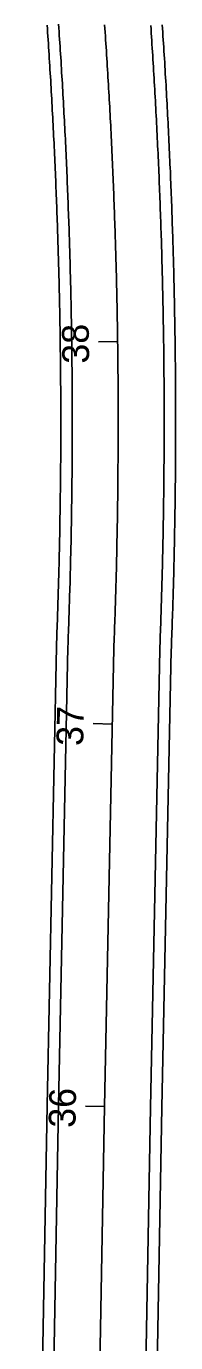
# Model space of a CAD drawing. Extents: x 2318076 to 2324211, y 613525 to 629939.
# Drawn here: x 2318913.8 to 2318952.8, y 618473.3 to 618817.4 of the extents above; entities that cross this region are included whole.
import ezdxf

# ---------------------------------------------------------------- set-up
doc = ezdxf.new("R2010")
doc.units = 0
for name, color, linetype in [('GE_P_CL_50', 7, 'Continuous'), ('PV_P_EOP', 7, 'Continuous'), ('PV_P_Shoulder', 7, 'Continuous')]:
    doc.layers.add(name, color=color, linetype=linetype)

msp = doc.modelspace()

# ---------------------------------------------------------------- linework, layer by layer
at = {"layer": 'GE_P_CL_50'}
for p, q in [((2318937.67, 618735), (2318932.67, 618734.93)), ((2318936.28, 618635.02), (2318931.28, 618635.12)), ((2318934.25, 618535.04), (2318929.25, 618535.14))]:
    msp.add_line(p, q, dxfattribs=at)
msp.add_lwpolyline([(2318928.83, 618235.09), (2318934.25, 618535.04), (2318936.67, 618654.75), (2318936.71, 618655.73), (2318936.74, 618656.7), (2318936.78, 618657.68), (2318936.82, 618658.66), (2318936.85, 618659.63), (2318936.89, 618660.61), (2318936.92, 618661.58), (2318936.95, 618662.56), (2318936.99, 618663.54), (2318937.02, 618664.51), (2318937.05, 618665.49), (2318937.08, 618666.47), (2318937.11, 618667.44), (2318937.14, 618668.42), (2318937.17, 618669.4), (2318937.2, 618670.37), (2318937.22, 618671.35), (2318937.25, 618672.33), (2318937.28, 618673.3), (2318937.3, 618674.28), (2318937.33, 618675.26), (2318937.35, 618676.23), (2318937.38, 618677.21), (2318937.4, 618678.18), (2318937.42, 618679.16), (2318937.44, 618680.14), (2318937.46, 618681.12), (2318937.48, 618682.09), (2318937.5, 618683.07), (2318937.52, 618684.05), (2318937.54, 618685.02), (2318937.56, 618686), (2318937.58, 618686.98), (2318937.6, 618687.95), (2318937.61, 618688.93), (2318937.63, 618689.91), (2318937.64, 618690.88), (2318937.66, 618691.86), (2318937.67, 618692.84), (2318937.68, 618693.81), (2318937.7, 618694.79), (2318937.71, 618695.77), (2318937.72, 618696.74), (2318937.73, 618697.72), (2318937.74, 618698.7), (2318937.75, 618699.67), (2318937.76, 618700.65), (2318937.79, 618705.54), (2318937.8, 618706.51), (2318937.8, 618707.49), (2318937.81, 618708.47), (2318937.81, 618709.44), (2318937.81, 618710.42), (2318937.81, 618711.4), (2318937.82, 618712.37), (2318937.82, 618713.35), (2318937.82, 618714.33), (2318937.82, 618715.31), (2318937.81, 618716.28), (2318937.81, 618717.26), (2318937.81, 618718.24), (2318937.81, 618719.21), (2318937.8, 618720.19), (2318937.8, 618721.17), (2318937.79, 618722.14), (2318937.79, 618723.12), (2318937.78, 618724.1), (2318937.78, 618725.07), (2318937.77, 618726.05), (2318937.76, 618727.03), (2318937.75, 618728.01), (2318937.74, 618728.98), (2318937.73, 618729.96), (2318937.72, 618730.94), (2318937.71, 618731.91), (2318937.7, 618732.89), (2318937.69, 618733.87), (2318937.67, 618734.84), (2318937.66, 618735.82), (2318937.65, 618736.8), (2318937.63, 618737.77), (2318937.61, 618738.75), (2318937.6, 618739.73), (2318937.58, 618740.7), (2318937.56, 618741.68), (2318937.55, 618742.66), (2318937.53, 618743.63), (2318937.51, 618744.61), (2318937.49, 618745.59), (2318937.47, 618746.56), (2318937.45, 618747.54), (2318937.42, 618748.52), (2318937.4, 618749.49), (2318937.38, 618750.47), (2318937.36, 618751.45), (2318937.33, 618752.42), (2318937.31, 618753.4), (2318937.28, 618754.38), (2318937.25, 618755.35), (2318937.23, 618756.33), (2318937.2, 618757.31), (2318937.17, 618758.28), (2318937.14, 618759.26), (2318937.11, 618760.24), (2318937.08, 618761.21), (2318937.05, 618762.19), (2318937.02, 618763.17), (2318936.99, 618764.14), (2318936.96, 618765.12), (2318936.93, 618766.1), (2318936.89, 618767.07), (2318936.86, 618768.05), (2318936.82, 618769.02), (2318936.79, 618770), (2318936.75, 618770.98), (2318936.71, 618771.95), (2318936.68, 618772.93), (2318936.64, 618773.91), (2318936.6, 618774.88), (2318936.56, 618775.86), (2318936.52, 618776.83), (2318936.48, 618777.81), (2318936.44, 618778.79), (2318936.4, 618779.76), (2318936.35, 618780.74), (2318936.31, 618781.71), (2318936.27, 618782.69), (2318936.22, 618783.67), (2318936.18, 618784.64), (2318936.13, 618785.62), (2318936.09, 618786.59), (2318936.04, 618787.57), (2318935.99, 618788.54), (2318935.94, 618789.52), (2318935.9, 618790.5), (2318935.85, 618791.47), (2318935.8, 618792.45), (2318935.75, 618793.42), (2318935.7, 618794.4), (2318935.64, 618795.37), (2318935.59, 618796.35), (2318935.54, 618797.33), (2318935.48, 618798.3), (2318935.43, 618799.28), (2318935.38, 618800.25), (2318935.32, 618801.23), (2318935.26, 618802.2), (2318935.21, 618803.18), (2318935.15, 618804.15), (2318935.09, 618805.13), (2318935.03, 618806.1), (2318934.97, 618807.08), (2318934.91, 618808.05), (2318934.85, 618809.03), (2318934.79, 618810), (2318934.73, 618810.98), (2318934.67, 618811.95), (2318934.61, 618812.93), (2318934.54, 618813.9), (2318934.48, 618814.88), (2318934.41, 618815.85), (2318934.35, 618816.83), (2318934.28, 618817.8)], dxfattribs=at)
at = {"layer": 'PV_P_EOP'}
for points in [[(2318916.83, 618235.27), (2318922.25, 618535.27), (2318924.67, 618655.1), (2318924.72, 618656.18), (2318924.75, 618657.15), (2318924.79, 618658.12), (2318924.82, 618659.09), (2318924.86, 618660.06), (2318924.89, 618661.03), (2318924.93, 618662), (2318924.96, 618662.96), (2318924.99, 618663.93), (2318925.02, 618664.9), (2318925.05, 618665.87), (2318925.08, 618666.84), (2318925.11, 618667.81), (2318925.14, 618668.78), (2318925.17, 618669.75), (2318925.2, 618670.71), (2318925.23, 618671.68), (2318925.25, 618672.65), (2318925.28, 618673.62), (2318925.31, 618674.59), (2318925.33, 618675.56), (2318925.36, 618676.53), (2318925.38, 618677.5), (2318925.4, 618678.47), (2318925.42, 618679.43), (2318925.45, 618680.4), (2318925.47, 618681.37), (2318925.49, 618682.34), (2318925.51, 618683.31), (2318925.53, 618684.28), (2318925.55, 618685.25), (2318925.56, 618686.22), (2318925.58, 618687.19), (2318925.6, 618688.16), (2318925.61, 618689.13), (2318925.63, 618690.09), (2318925.64, 618691.06), (2318925.66, 618692.03), (2318925.67, 618693), (2318925.69, 618693.97), (2318925.7, 618694.94), (2318925.71, 618695.91), (2318925.72, 618696.88), (2318925.73, 618697.85), (2318925.74, 618698.82), (2318925.75, 618699.79), (2318925.76, 618700.75), (2318925.79, 618705.61), (2318925.8, 618706.57), (2318925.8, 618707.54), (2318925.81, 618708.51), (2318925.81, 618709.48), (2318925.81, 618710.45), (2318925.81, 618711.42), (2318925.82, 618712.39), (2318925.82, 618713.36), (2318925.82, 618714.33), (2318925.82, 618715.29), (2318925.81, 618716.26), (2318925.81, 618717.23), (2318925.81, 618718.2), (2318925.81, 618719.17), (2318925.8, 618720.14), (2318925.8, 618721.11), (2318925.79, 618722.08), (2318925.79, 618723.05), (2318925.78, 618724.02), (2318925.78, 618724.99), (2318925.77, 618725.96), (2318925.76, 618726.93), (2318925.75, 618727.89), (2318925.74, 618728.86), (2318925.73, 618729.83), (2318925.72, 618730.8), (2318925.71, 618731.77), (2318925.7, 618732.74), (2318925.69, 618733.71), (2318925.67, 618734.68), (2318925.66, 618735.65), (2318925.65, 618736.62), (2318925.63, 618737.59), (2318925.62, 618738.56), (2318925.6, 618739.52), (2318925.58, 618740.49), (2318925.57, 618741.46), (2318925.55, 618742.43), (2318925.53, 618743.4), (2318925.51, 618744.37), (2318925.49, 618745.34), (2318925.47, 618746.31), (2318925.45, 618747.28), (2318925.43, 618748.25), (2318925.41, 618749.22), (2318925.38, 618750.18), (2318925.36, 618751.15), (2318925.33, 618752.12), (2318925.31, 618753.09), (2318925.28, 618754.06), (2318925.26, 618755.03), (2318925.23, 618756), (2318925.21, 618756.97), (2318925.18, 618757.94), (2318925.15, 618758.9), (2318925.12, 618759.87), (2318925.09, 618760.84), (2318925.06, 618761.81), (2318925.03, 618762.78), (2318925, 618763.75), (2318924.97, 618764.72), (2318924.93, 618765.69), (2318924.9, 618766.65), (2318924.86, 618767.62), (2318924.83, 618768.59), (2318924.79, 618769.56), (2318924.76, 618770.53), (2318924.72, 618771.5), (2318924.69, 618772.47), (2318924.65, 618773.43), (2318924.61, 618774.4), (2318924.57, 618775.37), (2318924.53, 618776.34), (2318924.49, 618777.31), (2318924.45, 618778.28), (2318924.41, 618779.24), (2318924.37, 618780.21), (2318924.32, 618781.18), (2318924.28, 618782.15), (2318924.24, 618783.12), (2318924.19, 618784.09), (2318924.15, 618785.05), (2318924.1, 618786.02), (2318924.05, 618786.99), (2318924.01, 618787.96), (2318923.96, 618788.93), (2318923.91, 618789.89), (2318923.86, 618790.86), (2318923.81, 618791.83), (2318923.76, 618792.8), (2318923.71, 618793.77), (2318923.66, 618794.73), (2318923.61, 618795.7), (2318923.56, 618796.67), (2318923.5, 618797.64), (2318923.45, 618798.61), (2318923.39, 618799.57), (2318923.34, 618800.54), (2318923.28, 618801.51), (2318923.23, 618802.48), (2318923.17, 618803.44), (2318923.11, 618804.41), (2318923.05, 618805.38), (2318923, 618806.35), (2318922.94, 618807.31), (2318922.88, 618808.28), (2318922.82, 618809.25), (2318922.75, 618810.22), (2318922.69, 618811.18), (2318922.63, 618812.15), (2318922.57, 618813.12), (2318922.5, 618814.08), (2318922.44, 618815.05), (2318922.37, 618816.02), (2318922.31, 618816.99), (2318922.24, 618817.95)], [(2318940.83, 618234.92), (2318946.25, 618534.81), (2318948.67, 618654.4), (2318948.7, 618655.27), (2318948.74, 618656.25), (2318948.77, 618657.24), (2318948.81, 618658.22), (2318948.84, 618659.2), (2318948.88, 618660.19), (2318948.91, 618661.17), (2318948.95, 618662.16), (2318948.98, 618663.14), (2318949.01, 618664.13), (2318949.04, 618665.11), (2318949.07, 618666.09), (2318949.1, 618667.08), (2318949.13, 618668.06), (2318949.16, 618669.05), (2318949.19, 618670.03), (2318949.22, 618671.01), (2318949.25, 618672), (2318949.27, 618672.98), (2318949.3, 618673.97), (2318949.32, 618674.95), (2318949.35, 618675.94), (2318949.37, 618676.92), (2318949.4, 618677.9), (2318949.42, 618678.89), (2318949.44, 618679.87), (2318949.46, 618680.86), (2318949.48, 618681.84), (2318949.5, 618682.83), (2318949.52, 618683.81), (2318949.54, 618684.79), (2318949.56, 618685.78), (2318949.58, 618686.76), (2318949.59, 618687.75), (2318949.61, 618688.73), (2318949.63, 618689.72), (2318949.64, 618690.7), (2318949.66, 618691.69), (2318949.67, 618692.67), (2318949.68, 618693.66), (2318949.7, 618694.64), (2318949.71, 618695.62), (2318949.72, 618696.61), (2318949.73, 618697.59), (2318949.74, 618698.58), (2318949.75, 618699.56), (2318949.76, 618700.55), (2318949.79, 618705.46), (2318949.8, 618706.45), (2318949.8, 618707.44), (2318949.81, 618708.42), (2318949.81, 618709.41), (2318949.81, 618710.39), (2318949.81, 618711.38), (2318949.82, 618712.36), (2318949.82, 618713.35), (2318949.82, 618714.33), (2318949.82, 618715.32), (2318949.81, 618716.3), (2318949.81, 618717.29), (2318949.81, 618718.27), (2318949.81, 618719.25), (2318949.8, 618720.24), (2318949.8, 618721.22), (2318949.79, 618722.21), (2318949.79, 618723.19), (2318949.78, 618724.18), (2318949.78, 618725.16), (2318949.77, 618726.15), (2318949.76, 618727.13), (2318949.75, 618728.12), (2318949.74, 618729.1), (2318949.73, 618730.08), (2318949.72, 618731.07), (2318949.71, 618732.05), (2318949.7, 618733.04), (2318949.69, 618734.02), (2318949.67, 618735.01), (2318949.66, 618735.99), (2318949.64, 618736.98), (2318949.63, 618737.96), (2318949.61, 618738.95), (2318949.6, 618739.93), (2318949.58, 618740.91), (2318949.56, 618741.9), (2318949.54, 618742.88), (2318949.53, 618743.87), (2318949.51, 618744.85), (2318949.49, 618745.84), (2318949.46, 618746.82), (2318949.44, 618747.81), (2318949.42, 618748.79), (2318949.4, 618749.77), (2318949.38, 618750.76), (2318949.35, 618751.74), (2318949.33, 618752.73), (2318949.3, 618753.71), (2318949.28, 618754.7), (2318949.25, 618755.68), (2318949.22, 618756.66), (2318949.2, 618757.65), (2318949.17, 618758.63), (2318949.14, 618759.62), (2318949.11, 618760.6), (2318949.08, 618761.58), (2318949.05, 618762.57), (2318949.02, 618763.55), (2318948.98, 618764.54), (2318948.95, 618765.52), (2318948.92, 618766.51), (2318948.88, 618767.49), (2318948.85, 618768.47), (2318948.81, 618769.46), (2318948.78, 618770.44), (2318948.74, 618771.42), (2318948.71, 618772.41), (2318948.67, 618773.39), (2318948.63, 618774.38), (2318948.59, 618775.36), (2318948.55, 618776.34), (2318948.51, 618777.33), (2318948.47, 618778.31), (2318948.43, 618779.3), (2318948.39, 618780.28), (2318948.34, 618781.26), (2318948.3, 618782.25), (2318948.26, 618783.23), (2318948.21, 618784.21), (2318948.17, 618785.2), (2318948.12, 618786.18), (2318948.07, 618787.16), (2318948.03, 618788.15), (2318947.98, 618789.13), (2318947.93, 618790.11), (2318947.88, 618791.1), (2318947.83, 618792.08), (2318947.78, 618793.06), (2318947.73, 618794.05), (2318947.68, 618795.03), (2318947.63, 618796.01), (2318947.57, 618797), (2318947.52, 618797.98), (2318947.47, 618798.96), (2318947.41, 618799.95), (2318947.36, 618800.93), (2318947.3, 618801.91), (2318947.24, 618802.9), (2318947.19, 618803.88), (2318947.13, 618804.86), (2318947.07, 618805.84), (2318947.01, 618806.83), (2318946.95, 618807.81), (2318946.89, 618808.79), (2318946.83, 618809.78), (2318946.77, 618810.76), (2318946.71, 618811.74), (2318946.64, 618812.72), (2318946.58, 618813.71), (2318946.52, 618814.69), (2318946.45, 618815.67), (2318946.39, 618816.65), (2318946.32, 618817.64)]]:
    msp.add_lwpolyline(points, dxfattribs=at)
at = {"layer": 'PV_P_Shoulder'}
for points in [[(2318913.83, 618235.32), (2318919.25, 618535.32), (2318921.68, 618655.19), (2318921.72, 618656.3), (2318921.75, 618657.26), (2318921.79, 618658.23), (2318921.83, 618659.2), (2318921.86, 618660.16), (2318921.89, 618661.13), (2318921.93, 618662.1), (2318921.96, 618663.06), (2318921.99, 618664.03), (2318922.03, 618665), (2318922.06, 618665.97), (2318922.09, 618666.93), (2318922.12, 618667.9), (2318922.15, 618668.87), (2318922.17, 618669.83), (2318922.2, 618670.8), (2318922.23, 618671.77), (2318922.26, 618672.73), (2318922.28, 618673.7), (2318922.31, 618674.67), (2318922.33, 618675.63), (2318922.36, 618676.6), (2318922.38, 618677.57), (2318922.4, 618678.54), (2318922.42, 618679.5), (2318922.45, 618680.47), (2318922.47, 618681.44), (2318922.49, 618682.4), (2318922.51, 618683.37), (2318922.53, 618684.34), (2318922.55, 618685.31), (2318922.56, 618686.27), (2318922.58, 618687.24), (2318922.6, 618688.21), (2318922.61, 618689.17), (2318922.63, 618690.14), (2318922.64, 618691.11), (2318922.66, 618692.08), (2318922.67, 618693.04), (2318922.69, 618694.01), (2318922.7, 618694.98), (2318922.71, 618695.95), (2318922.72, 618696.91), (2318922.73, 618697.88), (2318922.74, 618698.85), (2318922.75, 618699.81), (2318922.76, 618700.77), (2318922.79, 618705.63), (2318922.8, 618706.59), (2318922.8, 618707.55), (2318922.81, 618708.52), (2318922.81, 618709.49), (2318922.81, 618710.45), (2318922.81, 618711.42), (2318922.82, 618712.39), (2318922.82, 618713.36), (2318922.82, 618714.32), (2318922.82, 618715.29), (2318922.81, 618716.26), (2318922.81, 618717.23), (2318922.81, 618718.19), (2318922.81, 618719.16), (2318922.8, 618720.13), (2318922.8, 618721.1), (2318922.79, 618722.06), (2318922.79, 618723.03), (2318922.78, 618724), (2318922.78, 618724.96), (2318922.77, 618725.93), (2318922.76, 618726.9), (2318922.75, 618727.87), (2318922.74, 618728.83), (2318922.73, 618729.8), (2318922.72, 618730.77), (2318922.71, 618731.74), (2318922.7, 618732.7), (2318922.69, 618733.67), (2318922.67, 618734.64), (2318922.66, 618735.6), (2318922.65, 618736.57), (2318922.63, 618737.54), (2318922.62, 618738.51), (2318922.6, 618739.47), (2318922.58, 618740.44), (2318922.57, 618741.41), (2318922.55, 618742.38), (2318922.53, 618743.34), (2318922.51, 618744.31), (2318922.49, 618745.28), (2318922.47, 618746.24), (2318922.45, 618747.21), (2318922.43, 618748.18), (2318922.41, 618749.15), (2318922.38, 618750.11), (2318922.36, 618751.08), (2318922.34, 618752.05), (2318922.31, 618753.01), (2318922.29, 618753.98), (2318922.26, 618754.95), (2318922.23, 618755.91), (2318922.21, 618756.88), (2318922.18, 618757.85), (2318922.15, 618758.82), (2318922.12, 618759.78), (2318922.09, 618760.75), (2318922.06, 618761.72), (2318922.03, 618762.68), (2318922, 618763.65), (2318921.97, 618764.62), (2318921.93, 618765.58), (2318921.9, 618766.55), (2318921.87, 618767.52), (2318921.83, 618768.48), (2318921.8, 618769.45), (2318921.76, 618770.42), (2318921.72, 618771.38), (2318921.69, 618772.35), (2318921.65, 618773.32), (2318921.61, 618774.28), (2318921.57, 618775.25), (2318921.53, 618776.22), (2318921.49, 618777.18), (2318921.45, 618778.15), (2318921.41, 618779.12), (2318921.37, 618780.08), (2318921.33, 618781.05), (2318921.28, 618782.01), (2318921.24, 618782.98), (2318921.19, 618783.95), (2318921.15, 618784.91), (2318921.1, 618785.88), (2318921.06, 618786.85), (2318921.01, 618787.81), (2318920.96, 618788.78), (2318920.92, 618789.74), (2318920.87, 618790.71), (2318920.82, 618791.68), (2318920.77, 618792.64), (2318920.72, 618793.61), (2318920.66, 618794.57), (2318920.61, 618795.54), (2318920.56, 618796.51), (2318920.51, 618797.47), (2318920.45, 618798.44), (2318920.4, 618799.4), (2318920.34, 618800.37), (2318920.29, 618801.34), (2318920.23, 618802.3), (2318920.18, 618803.27), (2318920.12, 618804.23), (2318920.06, 618805.2), (2318920, 618806.16), (2318919.94, 618807.13), (2318919.88, 618808.09), (2318919.82, 618809.06), (2318919.76, 618810.03), (2318919.7, 618810.99), (2318919.64, 618811.96), (2318919.57, 618812.92), (2318919.51, 618813.89), (2318919.45, 618814.85), (2318919.38, 618815.82), (2318919.32, 618816.78), (2318919.25, 618817.75)], [(2318943.83, 618234.87), (2318949.25, 618534.75), (2318951.66, 618654.31), (2318951.7, 618655.15), (2318951.73, 618656.14), (2318951.77, 618657.13), (2318951.81, 618658.11), (2318951.84, 618659.1), (2318951.88, 618660.08), (2318951.91, 618661.07), (2318951.94, 618662.06), (2318951.98, 618663.04), (2318952.01, 618664.03), (2318952.04, 618665.01), (2318952.07, 618666), (2318952.1, 618666.99), (2318952.13, 618667.97), (2318952.16, 618668.96), (2318952.19, 618669.94), (2318952.22, 618670.93), (2318952.24, 618671.92), (2318952.27, 618672.9), (2318952.3, 618673.89), (2318952.32, 618674.88), (2318952.35, 618675.86), (2318952.37, 618676.85), (2318952.39, 618677.83), (2318952.42, 618678.82), (2318952.44, 618679.81), (2318952.46, 618680.79), (2318952.48, 618681.78), (2318952.5, 618682.77), (2318952.52, 618683.75), (2318952.54, 618684.74), (2318952.56, 618685.72), (2318952.58, 618686.71), (2318952.59, 618687.7), (2318952.61, 618688.68), (2318952.63, 618689.67), (2318952.64, 618690.66), (2318952.66, 618691.64), (2318952.67, 618692.63), (2318952.68, 618693.62), (2318952.7, 618694.6), (2318952.71, 618695.59), (2318952.72, 618696.58), (2318952.73, 618697.56), (2318952.74, 618698.55), (2318952.75, 618699.53), (2318952.76, 618700.53), (2318952.79, 618705.44), (2318952.8, 618706.44), (2318952.8, 618707.43), (2318952.81, 618708.41), (2318952.81, 618709.4), (2318952.81, 618710.39), (2318952.81, 618711.37), (2318952.82, 618712.36), (2318952.82, 618713.35), (2318952.82, 618714.33), (2318952.82, 618715.32), (2318952.81, 618716.31), (2318952.81, 618717.29), (2318952.81, 618718.28), (2318952.81, 618719.26), (2318952.8, 618720.25), (2318952.8, 618721.24), (2318952.79, 618722.22), (2318952.79, 618723.21), (2318952.78, 618724.2), (2318952.78, 618725.18), (2318952.77, 618726.17), (2318952.76, 618727.16), (2318952.75, 618728.14), (2318952.74, 618729.13), (2318952.73, 618730.12), (2318952.72, 618731.1), (2318952.71, 618732.09), (2318952.7, 618733.08), (2318952.68, 618734.06), (2318952.67, 618735.05), (2318952.66, 618736.03), (2318952.64, 618737.02), (2318952.63, 618738.01), (2318952.61, 618738.99), (2318952.6, 618739.98), (2318952.58, 618740.97), (2318952.56, 618741.95), (2318952.54, 618742.94), (2318952.52, 618743.93), (2318952.51, 618744.91), (2318952.48, 618745.9), (2318952.46, 618746.88), (2318952.44, 618747.87), (2318952.42, 618748.86), (2318952.4, 618749.84), (2318952.37, 618750.83), (2318952.35, 618751.82), (2318952.33, 618752.8), (2318952.3, 618753.79), (2318952.28, 618754.77), (2318952.25, 618755.76), (2318952.22, 618756.75), (2318952.19, 618757.73), (2318952.17, 618758.72), (2318952.14, 618759.71), (2318952.11, 618760.69), (2318952.08, 618761.68), (2318952.05, 618762.66), (2318952.01, 618763.65), (2318951.98, 618764.64), (2318951.95, 618765.62), (2318951.92, 618766.61), (2318951.88, 618767.59), (2318951.85, 618768.58), (2318951.81, 618769.57), (2318951.78, 618770.55), (2318951.74, 618771.54), (2318951.7, 618772.52), (2318951.67, 618773.51), (2318951.63, 618774.49), (2318951.59, 618775.48), (2318951.55, 618776.47), (2318951.51, 618777.45), (2318951.47, 618778.44), (2318951.43, 618779.42), (2318951.38, 618780.41), (2318951.34, 618781.39), (2318951.3, 618782.38), (2318951.25, 618783.36), (2318951.21, 618784.35), (2318951.16, 618785.34), (2318951.12, 618786.32), (2318951.07, 618787.31), (2318951.02, 618788.29), (2318950.97, 618789.28), (2318950.93, 618790.26), (2318950.88, 618791.25), (2318950.83, 618792.23), (2318950.78, 618793.22), (2318950.73, 618794.2), (2318950.67, 618795.19), (2318950.62, 618796.17), (2318950.57, 618797.16), (2318950.52, 618798.14), (2318950.46, 618799.13), (2318950.41, 618800.11), (2318950.35, 618801.1), (2318950.3, 618802.08), (2318950.24, 618803.07), (2318950.18, 618804.05), (2318950.12, 618805.04), (2318950.06, 618806.02), (2318950.01, 618807.01), (2318949.95, 618807.99), (2318949.89, 618808.98), (2318949.82, 618809.96), (2318949.76, 618810.95), (2318949.7, 618811.93), (2318949.64, 618812.92), (2318949.57, 618813.9), (2318949.51, 618814.88), (2318949.44, 618815.87), (2318949.38, 618816.85), (2318949.31, 618817.84)]]:
    msp.add_lwpolyline(points, dxfattribs=at)

# ---------------------------------------------------------------- texts
at = {"layer": 'GE_P_CL_50'}
for s, rotation, p in [('38', 90.8029, (2318930.25, 618729.27)), ('37', 88.8653, (2318928.66, 618629.24)), ('36', 88.7923, (2318926.63, 618529.41))]:
    msp.add_text(s, height=7, rotation=rotation, dxfattribs=at).set_placement(p)

doc.saveas('drawing.dxf')
